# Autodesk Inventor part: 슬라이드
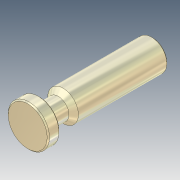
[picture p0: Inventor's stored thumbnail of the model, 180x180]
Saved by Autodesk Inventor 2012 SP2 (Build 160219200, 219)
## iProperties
Company: 한국ATC센터
Created: 2014-11
Part Number: 슬라이드
Document SubType Name: Modeling
Designer: KYOUNG IL JANG
Density: 7.86 g/cm^3
Material: 강, 연강
Mass: 436.103 g
Surface Area: 105.764 cm^2
Volume: 55.4838 cm^3
Author: KYOUNG IL JANG
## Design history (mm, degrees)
sketch "스케치1"
  geometry: L1 (19, 106.5)-(-19, 106.5) reference; L2 (0, 106.5)-(0, 212.5); L3 (0, 212.5)-(-13, 212.5); L4 (-13, 212.5)-(-13, 136.5); L5 (-9, 116.5)-(-17.5, 116.5); L6 (-17.5, 116.5)-(-17.5, 106.5); L7 (-17.5, 106.5)-(0, 106.5); L8 (-9, 116.5)-(-9, 132.5); L9 (-9, 132.5)-(-13, 136.5); 1 further point
  constraints: 18 end point, 3 perpendicular, 1 collinear, 1 horizontal, 1 midpoint, 1 parallel, 2 other
  dimensions: "d0" = 10 distance between parallel lines of L5 L7; "d1" = 35 diameter of L6 L2; "d2" = 106 distance of L2.start L2.end; "d3" = 135 deg angle of L9 L4; "d4" = 18 diameter of L8 L2; "d5" = 30 distance from line of L4.end L7; "d11" = 26 diameter of L4 L2
revolve "회전1" sketch "스케치1" stored, may be unused: angle "d6" = 90 deg
chamfer "모따기1" distance "d7" = 1; stored, may be unused: second distance "d8" = 2, angle "d9" = 45 deg
fillet "모깎기1" dims "d10" = 2
node "솔리드1"
